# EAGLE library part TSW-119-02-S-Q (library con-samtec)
THROUGH-HOLE .025" SQ POST HEADER Source: Samtec TSW.pdf
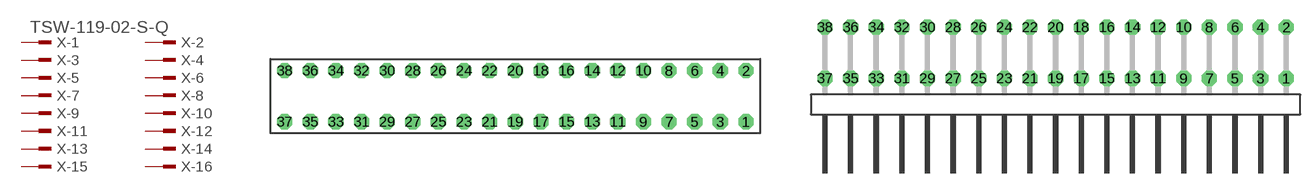
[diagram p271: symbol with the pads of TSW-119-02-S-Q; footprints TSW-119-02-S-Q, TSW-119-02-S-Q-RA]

Designator prefix X; gates -1=MPINV -2=MPIN -3=MPIN -4=MPIN -5=MPIN -6=MPIN -7=MPIN -8=MPIN -9=MPIN -10=MPIN -11=MPIN -12=MPIN -13=MPIN -14=MPIN -15=MPIN -16=MPIN -17=MPIN -18=MPIN -19=MPIN -20=MPIN -21=MPIN -22=MPIN -23=MPIN -24=MPIN -25=MPIN -26=MPIN -27=MPIN -28=MPIN -29=MPIN -30=MPIN -31=MPIN -32=MPIN -33=MPIN -34=MPIN -35=MPIN -36=MPIN -37=MPIN -38=MPIN

## TSW-119-02-S-Q (OC_FARNELL: unknown; OC_NEWARK: unknown)  [TSW-119-02-S-Q]
1  -1:1  pas
2  -2:1  pas
3  -3:1  pas
4  -4:1  pas
5  -5:1  pas
6  -6:1  pas
7  -7:1  pas
8  -8:1  pas
9  -9:1  pas
10  -10:1  pas
11  -11:1  pas
12  -12:1  pas
13  -13:1  pas
14  -14:1  pas
15  -15:1  pas
16  -16:1  pas
17  -17:1  pas
18  -18:1  pas
19  -19:1  pas
20  -20:1  pas
21  -21:1  pas
22  -22:1  pas
23  -23:1  pas
24  -24:1  pas
25  -25:1  pas
26  -26:1  pas
27  -27:1  pas
28  -28:1  pas
29  -29:1  pas
30  -30:1  pas
31  -31:1  pas
32  -32:1  pas
33  -33:1  pas
34  -34:1  pas
35  -35:1  pas
36  -36:1  pas
37  -37:1  pas
38  -38:1  pas

## TSW-119-02-S-Q-RA (OC_FARNELL: unknown; OC_NEWARK: unknown)  [TSW-119-02-S-Q-RA]
Pads as for TSW-119-02-S-Q

## Footprint TSW-119-02-S-Q (pad centres in mm)
THROUGH-HOLE .025" SQ POST HEADER Source: Samtec TSW.pdf
drill 1 pad 1.5 octagon: 1 22.86,-2.54; 2 22.86,2.54; 3 20.32,-2.54; 4 20.32,2.54; 5 17.78,-2.54; 6 17.78,2.54; 7 15.24,-2.54; 8 15.24,2.54; 9 12.7,-2.54; 10 12.7,2.54; 11 10.16,-2.54; 12 10.16,2.54; 13 7.62,-2.54; 14 7.62,2.54; 15 5.08,-2.54; 16 5.08,2.54; 17 2.54,-2.54; 18 2.54,2.54; 19 0,-2.54; 20 0,2.54; 21 -2.54,-2.54; 22 -2.54,2.54; 23 -5.08,-2.54; 24 -5.08,2.54; 25 -7.62,-2.54; 26 -7.62,2.54; 27 -10.16,-2.54; 28 -10.16,2.54; 29 -12.7,-2.54; 30 -12.7,2.54; 31 -15.24,-2.54; 32 -15.24,2.54; 33 -17.78,-2.54; 34 -17.78,2.54; 35 -20.32,-2.54; 36 -20.32,2.54; 37 -22.86,-2.54; 38 -22.86,2.54

## Footprint TSW-119-02-S-Q-RA (pad centres in mm)
THROUGH-HOLE .025" SQ POST HEADER Source: Samtec TSW.pdf
drill 1 pad 1.5 octagon: 1 22.86,1.524; 2 22.86,6.604; 3 20.32,1.524; 4 20.32,6.604; 5 17.78,1.524; 6 17.78,6.604; 7 15.24,1.524; 8 15.24,6.604; 9 12.7,1.524; 10 12.7,6.604; 11 10.16,1.524; 12 10.16,6.604; 13 7.62,1.524; 14 7.62,6.604; 15 5.08,1.524; 16 5.08,6.604; 17 2.54,1.524; 18 2.54,6.604; 19 0,1.524; 20 0,6.604; 21 -2.54,1.524; 22 -2.54,6.604; 23 -5.08,1.524; 24 -5.08,6.604; 25 -7.62,1.524; 26 -7.62,6.604; 27 -10.16,1.524; 28 -10.16,6.604; 29 -12.7,1.524; 30 -12.7,6.604; 31 -15.24,1.524; 32 -15.24,6.604; 33 -17.78,1.524; 34 -17.78,6.604; 35 -20.32,1.524; 36 -20.32,6.604; 37 -22.86,1.524; 38 -22.86,6.604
